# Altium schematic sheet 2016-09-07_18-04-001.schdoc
size 212 x 144 mm; SheetNumber: 1; SheetTotal: 1
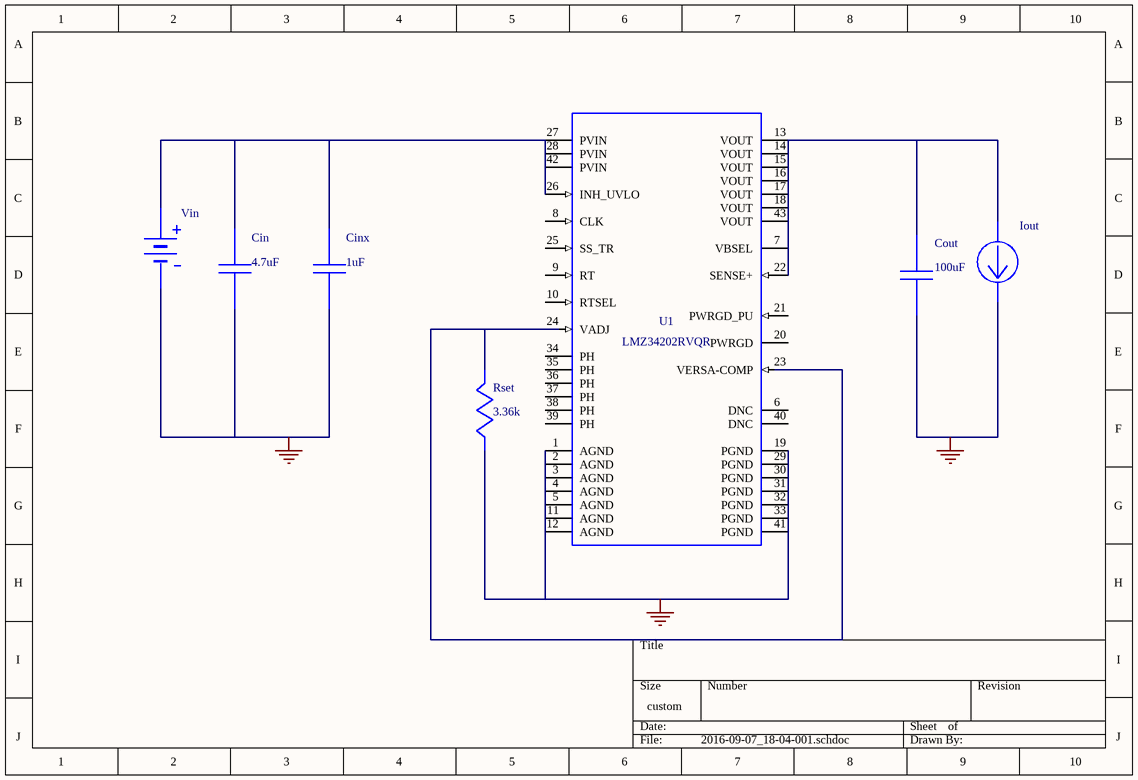
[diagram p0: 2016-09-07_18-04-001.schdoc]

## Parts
Cin  value 4.7uF  (hidden comment: GRM32ER71H475KA88L)
Cinx  value 1uF  (hidden comment: C3216X5R1H105K)
Cout  value 100uF  (hidden comment: GENERIC_CAPACITOR)
Iout  WB_CURRENT_LOAD  (value not drawn)
Rset  value 3.36k  (hidden comment: RT0805BRD073K36L)
U1  LMZ34202RVQR
Vin  WB_BATTERY  (value not drawn)

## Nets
0: Cin.2 Cinx.1 Cout.2 Iout.2(-) Rset.2 U1.1(AGND) U1.2(AGND) U1.3(AGND) U1.4(AGND) U1.5(AGND) U1.11(AGND) U1.12(AGND) U1.19(PGND) U1.29(PGND) U1.30(PGND) U1.31(PGND) U1.32(PGND) U1.33(PGND) U1.41(PGND) Vin.2(-)
NetCin_1: Cin.1 Cinx.2 U1.26(INH_UVLO) U1.27(PVIN) U1.28(PVIN) U1.42(PVIN) Vin.1(+)
NetCout_1: Cout.1 Iout.1(+) U1.7(VBSEL) U1.13(VOUT) U1.14(VOUT) U1.15(VOUT) U1.16(VOUT) U1.17(VOUT) U1.18(VOUT) U1.22(SENSE+) U1.43(VOUT)
NetRset_1: Rset.1 U1.23(VERSA-COMP) U1.24(VADJ)

Not connected (* = marked no-connect by the designer): U1 6(DNC) 8(CLK) 9(RT) 10(RTSEL) 20(PWRGD) 21(PWRGD_PU) 25(SS_TR) 34(PH) 35(PH) 36(PH) 37(PH) 38(PH) 39(PH) 40(DNC)

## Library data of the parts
Cin = GRM32ER71H475KA88L: GRM32ER71H475KA8; Manufacturer Name: MuRata
Cinx = C3216X5R1H105K: Manufacturer Name: TDK
Cout = GENERIC_CAPACITOR: 16SVPC100M; Manufacturer Name: Panasonic
Rset = RT0805BRD073K36L: Manufacturer Name: Yageo America
U1 = LMZ34202RVQR: Manufacturer Name: Texas Instruments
